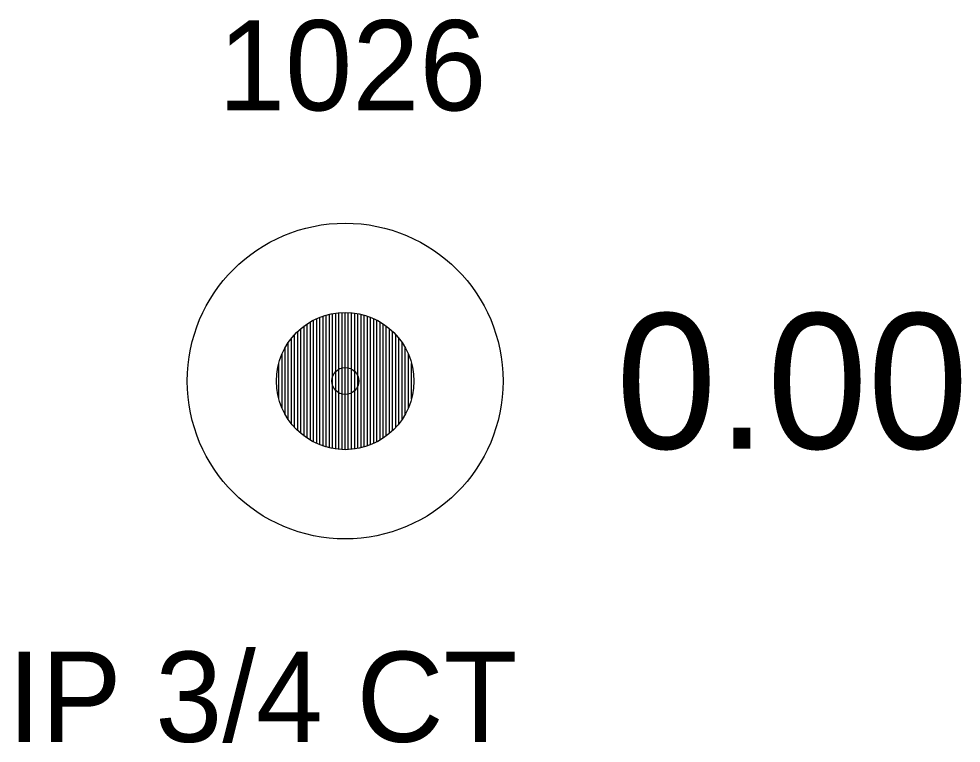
# Model space of a CAD drawing. Extents: x 1655137 to 1657928, y 1003994 to 1005407.
# Drawn here: x 1655434.36 to 1655444.8, y 1004557.25 to 1004565.28 of the extents above; entities that cross this region are included whole.
import ezdxf

# ---------------------------------------------------------------- set-up
doc = ezdxf.new("R2010")
doc.units = 0
for name, color, linetype in [('RD_EX_DV_Prop_txCode', 7, 'Continuous'), ('RD_EX_DV_PropPin', 7, 'Continuous'), ('RD_EX_TX_DV_Prop_ELEV', 7, 'Continuous'), ('RD_SMD_Locator', 7, 'Continuous')]:
    doc.layers.add(name, color=color, linetype=linetype)

msp = doc.modelspace()

# ---------------------------------------------------------------- linework, layer by layer
at = {"layer": 'RD_EX_DV_PropPin'}
for p, q in [((1655437.838, 1004560.514), (1655437.838, 1004562.01)), ((1655437.873, 1004560.508), (1655437.873, 1004562.016)), ((1655437.908, 1004560.504), (1655437.908, 1004562.02)), ((1655437.943, 1004560.502), (1655437.943, 1004562.022)), ((1655437.978, 1004560.501), (1655437.978, 1004562.023)), ((1655438.013, 1004560.502), (1655438.013, 1004562.022)), ((1655438.049, 1004560.504), (1655438.049, 1004562.02)), ((1655438.084, 1004560.508), (1655438.084, 1004562.016)), ((1655438.119, 1004560.514), (1655438.119, 1004562.01)), ((1655437.593, 1004560.606), (1655437.593, 1004561.918)), ((1655437.628, 1004560.586), (1655437.628, 1004561.938)), ((1655437.663, 1004560.569), (1655437.663, 1004561.955)), ((1655437.698, 1004560.554), (1655437.698, 1004561.969)), ((1655437.733, 1004560.541), (1655437.733, 1004561.982)), ((1655437.768, 1004560.53), (1655437.768, 1004561.993)), ((1655437.803, 1004560.521), (1655437.803, 1004562.003)), ((1655438.154, 1004560.521), (1655438.154, 1004562.003)), ((1655438.189, 1004560.53), (1655438.189, 1004561.993)), ((1655438.224, 1004560.541), (1655438.224, 1004561.982)), ((1655438.259, 1004560.554), (1655438.259, 1004561.969)), ((1655438.294, 1004560.569), (1655438.294, 1004561.955)), ((1655438.329, 1004560.586), (1655438.329, 1004561.938)), ((1655438.364, 1004560.606), (1655438.364, 1004561.918)), ((1655437.453, 1004560.711), (1655437.453, 1004561.813)), ((1655437.488, 1004560.68), (1655437.488, 1004561.844)), ((1655437.523, 1004560.652), (1655437.523, 1004561.872)), ((1655437.558, 1004560.627), (1655437.558, 1004561.896)), ((1655438.399, 1004560.627), (1655438.399, 1004561.896)), ((1655438.434, 1004560.652), (1655438.434, 1004561.872)), ((1655438.469, 1004560.68), (1655438.469, 1004561.844)), ((1655438.504, 1004560.711), (1655438.504, 1004561.813)), ((1655437.383, 1004560.788), (1655437.383, 1004561.736)), ((1655437.418, 1004560.747), (1655437.418, 1004561.777)), ((1655438.539, 1004560.747), (1655438.539, 1004561.777)), ((1655438.574, 1004560.788), (1655438.574, 1004561.736)), ((1655437.313, 1004560.892), (1655437.313, 1004561.631)), ((1655437.348, 1004560.835), (1655437.348, 1004561.688)), ((1655438.609, 1004560.835), (1655438.609, 1004561.688)), ((1655438.644, 1004560.892), (1655438.644, 1004561.631)), ((1655437.278, 1004560.964), (1655437.278, 1004561.56)), ((1655438.679, 1004560.964), (1655438.679, 1004561.56)), ((1655437.243, 1004561.066), (1655437.243, 1004561.458)), ((1655438.714, 1004561.066), (1655438.714, 1004561.458))]:
    msp.add_line(p, q, dxfattribs=at)
for radius in [1.75, 0.761]:
    msp.add_circle((1655437.978, 1004561.262), radius, dxfattribs=at)
at = {"layer": 'RD_SMD_Locator'}
msp.add_circle((1655437.979, 1004561.262), 0.15, dxfattribs=at)

# ---------------------------------------------------------------- texts
at = {"layer": 'RD_EX_DV_Prop_txCode'}
for s, p in [('1026', (1655436.569, 1004564.262)), ('IP 3/4 CT', (1655434.238, 1004557.262))]:
    msp.add_text(s, height=1, dxfattribs=at).set_placement(p)
at = {"layer": 'RD_EX_TX_DV_Prop_ELEV'}
msp.add_text('0.00', height=1.5, dxfattribs=at).set_placement((1655440.979, 1004560.512))

doc.saveas('drawing.dxf')
